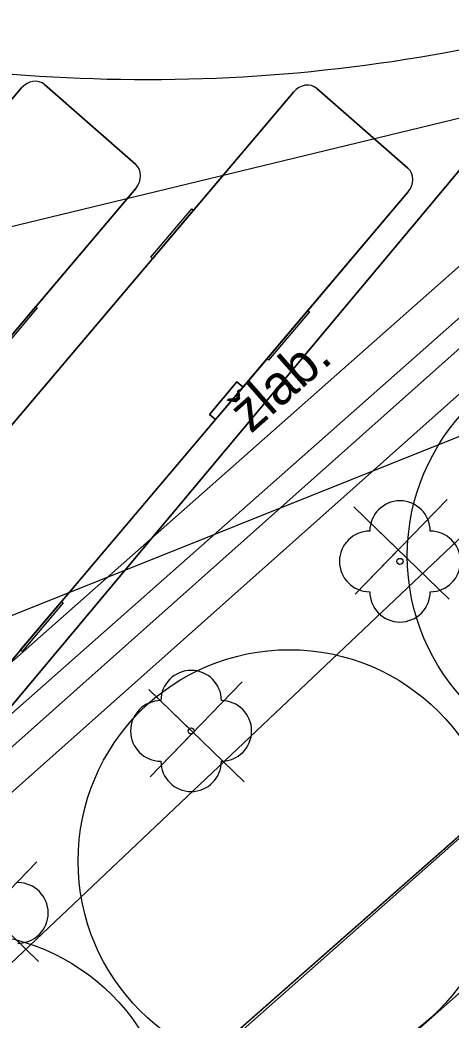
# Model space of a CAD drawing. Extents: x -438233 to -437334, y -1133133 to -1132623.
# Drawn here: x -438060.06 to -438052.93, y -1132995.04 to -1132978.53 of the extents above; entities that cross this region are included whole.
import ezdxf

# ---------------------------------------------------------------- set-up
doc = ezdxf.new("R2010")
doc.units = 0
for name, color, linetype in [('Vrstva 1', 7, 'Continuous'), ('Vrstva 10', 7, 'Continuous'), ('Vrstva 11', 7, 'Continuous'), ('Vrstva 22', 7, 'Continuous'), ('Vrstva 40', 7, 'Continuous'), ('Vrstva 55', 7, 'Continuous'), ('Vrstva 9', 7, 'Continuous')]:
    doc.layers.add(name, color=color, linetype=linetype)

msp = doc.modelspace()

# ---------------------------------------------------------------- linework, layer by layer
at = {"layer": 'Vrstva 1'}
for p, q in [((-438059.649, -1132979.598), (-438058.143, -1132980.914)), ((-438055.149, -1132979.662), (-438053.644, -1132980.977))]:
    msp.add_line(p, q, dxfattribs=at)
for points in [[(-438050.796, -1132978.629), (-438061.117, -1132990.948), (-438063.799, -1132988.701), (-438065.455, -1132990.677)], [(-438067.367, -1132988.444), (-438066.717, -1132987.54), (-438060.036, -1132979.658)], [(-438060.036, -1132979.658), (-438066.717, -1132987.54)], [(-438058.143, -1132980.914), (-438059.649, -1132979.598)], [(-438053.644, -1132980.977), (-438055.149, -1132979.662)], [(-438062.867, -1132988.507), (-438062.218, -1132987.603), (-438055.537, -1132979.722)], [(-438055.537, -1132979.722), (-438062.218, -1132987.603)], [(-438058.144, -1132981.312), (-438060.87, -1132984.527), (-438060.969, -1132984.44), (-438061.424, -1132984.976), (-438061.324, -1132985.063), (-438064.825, -1132989.193), (-438064.834, -1132989.202), (-438064.933, -1132989.115), (-438065.478, -1132989.657), (-438065.376, -1132989.746), (-438065.609, -1132989.98)], [(-438064.825, -1132989.193), (-438058.144, -1132981.312)], [(-438053.645, -1132981.375), (-438056.37, -1132984.59), (-438056.47, -1132984.503), (-438056.925, -1132985.04), (-438056.825, -1132985.127), (-438060.326, -1132989.257), (-438060.335, -1132989.265), (-438060.433, -1132989.179), (-438060.979, -1132989.72), (-438060.877, -1132989.809), (-438061.11, -1132990.043)], [(-438060.326, -1132989.257), (-438053.645, -1132981.375)]]:
    msp.add_lwpolyline(points, dxfattribs=at)
for points in [[(-438057.19, -1132981.672), (-438057.867, -1132982.471), (-438057.893, -1132982.448), (-438057.216, -1132981.649)], [(-438057.19, -1132981.672), (-438057.849, -1132982.449), (-438057.849, -1132982.449), (-438057.19, -1132981.672)], [(-438059.771, -1132983.284), (-438060.448, -1132984.083), (-438060.474, -1132984.06), (-438059.797, -1132983.261)], [(-438055.272, -1132983.348), (-438055.949, -1132984.147), (-438055.975, -1132984.124), (-438055.298, -1132983.325)], [(-438056.37, -1132984.59), (-438056.825, -1132985.127), (-438056.925, -1132985.04), (-438056.47, -1132984.503)], [(-438059.345, -1132988.153), (-438060.023, -1132988.952), (-438060.049, -1132988.929), (-438059.371, -1132988.13)]]:
    msp.add_lwpolyline(points, close=True, dxfattribs=at)
msp.add_arc((-438057.962, -1132951.913), 27.6, 255.0767, 285.0155, dxfattribs=at)
for centre, start_param, end_param in [((-438059.843, -1132979.827), 3.093695, 4.664491), ((-438059.843, -1132979.827), 3.093695, 4.664491), ((-438055.343, -1132979.89), 3.093695, 4.664491), ((-438055.343, -1132979.89), 3.093695, 4.664491), ((-438058.337, -1132981.143), 1.522899, 3.093695), ((-438058.337, -1132981.143), 1.522899, 3.093695), ((-438053.838, -1132981.206), 1.522899, 3.093695), ((-438053.838, -1132981.206), 1.522899, 3.093695)]:
    msp.add_ellipse(centre, major_axis=(-0.184, -0.237), ratio=0.855, start_param=start_param, end_param=end_param, dxfattribs=at)
at = {"layer": 'Vrstva 10'}
msp.add_lwpolyline([(-438035.457, -1132968.667), (-438040.579, -1132973.124), (-438048.857, -1132980.452), (-438065.053, -1132994.849), (-438072.69, -1133001.433), (-438073.961, -1133002.24), (-438075.077, -1133002.697), (-438076.272, -1133002.948)], dxfattribs=at)
at = {"layer": 'Vrstva 11'}
for points in [[(-438079.851, -1133001.541), (-438081.143, -1133003.836), (-438082.651, -1133014.98), (-438080.295, -1133016.157), (-438070.78, -1133008.056), (-438059.123, -1132997.555), (-438044.087, -1132984.346), (-438028.394, -1132970.577), (-438016.298, -1132960.009), (-438006.567, -1132951.363)], [(-438080.927, -1133019.451), (-438077.139, -1133016.254), (-438069.364, -1133009.292), (-438057.759, -1132998.987), (-438043.045, -1132985.96), (-438027.231, -1132972.034), (-438013.435, -1132960.019)], [(-438073.986, -1133001.3), (-438049.447, -1132979.638), (-438041.292, -1132972.525), (-438035.024, -1132966.82)], [(-438064.806, -1132994.051), (-438049.025, -1132980.119), (-438040.866, -1132973.003), (-438034.559, -1132967.262)]]:
    msp.add_lwpolyline(points, dxfattribs=at)
at = {"layer": 'Vrstva 22'}
for centre in [(-438053.776, -1132987.467), (-438057.228, -1132990.265)]:
    msp.add_circle(centre, 0.05, dxfattribs=at)
for centre, start, end in [((-438053.776, -1132986.967), 0, 180), ((-438054.276, -1132987.467), 90, 270), ((-438053.276, -1132987.467), 270, 90), ((-438053.776, -1132987.967), 180, 0), ((-438057.228, -1132989.765), 0, 180), ((-438057.728, -1132990.265), 90, 270), ((-438056.728, -1132990.265), 270, 90), ((-438057.228, -1132990.765), 180, 0), ((-438060.09, -1132993.269), 270, 90)]:
    msp.add_arc(centre, 0.5, start, end, dxfattribs=at)
at = {"layer": 'Vrstva 40'}
for p in [(-438072.81, -1132984.991), (-438067.038, -1132991.096)]:
    msp.add_line(p, (-438019.505, -1132972.094), dxfattribs=at)
for points in [[(-438006.567, -1132951.363), (-438080.295, -1133016.157), (-438085.207, -1133012.071), (-438080.546, -1133006.803), (-438077.182, -1133006.231), (-438076.556, -1133006.759), (-438075.914, -1133005.992), (-438066.402, -1132994.506), (-438073.034, -1132988.817), (-438072.353, -1132988.023), (-438069.665, -1132990.252), (-438068.287, -1132988.606), (-438065.604, -1132990.854), (-438063.799, -1132988.701), (-438061.117, -1132990.948), (-438050.796, -1132978.629), (-438047.72, -1132977.59), (-438045.204, -1132976.394), (-438042.678, -1132974.884), (-438040.928, -1132973.634), (-438039.59, -1132972.514), (-438037.876, -1132970.87), (-438035.397, -1132967.806), (-438020.007, -1132954.124)], [(-438052.997, -1132986.444), (-438054.517, -1132988.01), (-438053.805, -1132987.277), (-438054.538, -1132986.566), (-438052.966, -1132988.092)], [(-438056.385, -1132989.457), (-438057.905, -1132991.023), (-438057.194, -1132990.29), (-438057.927, -1132989.579), (-438056.354, -1132991.104)], [(-438059.78, -1132992.424), (-438061.299, -1132993.991), (-438060.588, -1132993.258), (-438061.321, -1132992.547), (-438059.749, -1132994.072)]]:
    msp.add_lwpolyline(points, dxfattribs=at)
for centre in [(-438050.167, -1132987.374), (-438055.606, -1132992.413), (-438061.006, -1132997.089)]:
    msp.add_circle(centre, 3.489, dxfattribs=at)
at = {"layer": 'Vrstva 55'}
for points in [[(-437982.978, -1132924.484), (-438038.365, -1132973.439), (-438076.856, -1133009.846)], [(-437979.821, -1132940.76), (-437988.363, -1132937.437), (-438041.643, -1132982.184), (-438086.636, -1133021.919)]]:
    msp.add_lwpolyline(points, dxfattribs=at)
at = {"layer": 'Vrstva 9'}
msp.add_lwpolyline([(-438046.991, -1132979.546), (-438048.487, -1132980.87), (-438063.628, -1132994.33)], dxfattribs=at)

# ---------------------------------------------------------------- texts
at = {"layer": 'Vrstva 40'}
msp.add_text('žlab.', height=0.65, rotation=41.4367, dxfattribs=at).set_placement((-438056.239, -1132985.367))

doc.saveas('drawing.dxf')
